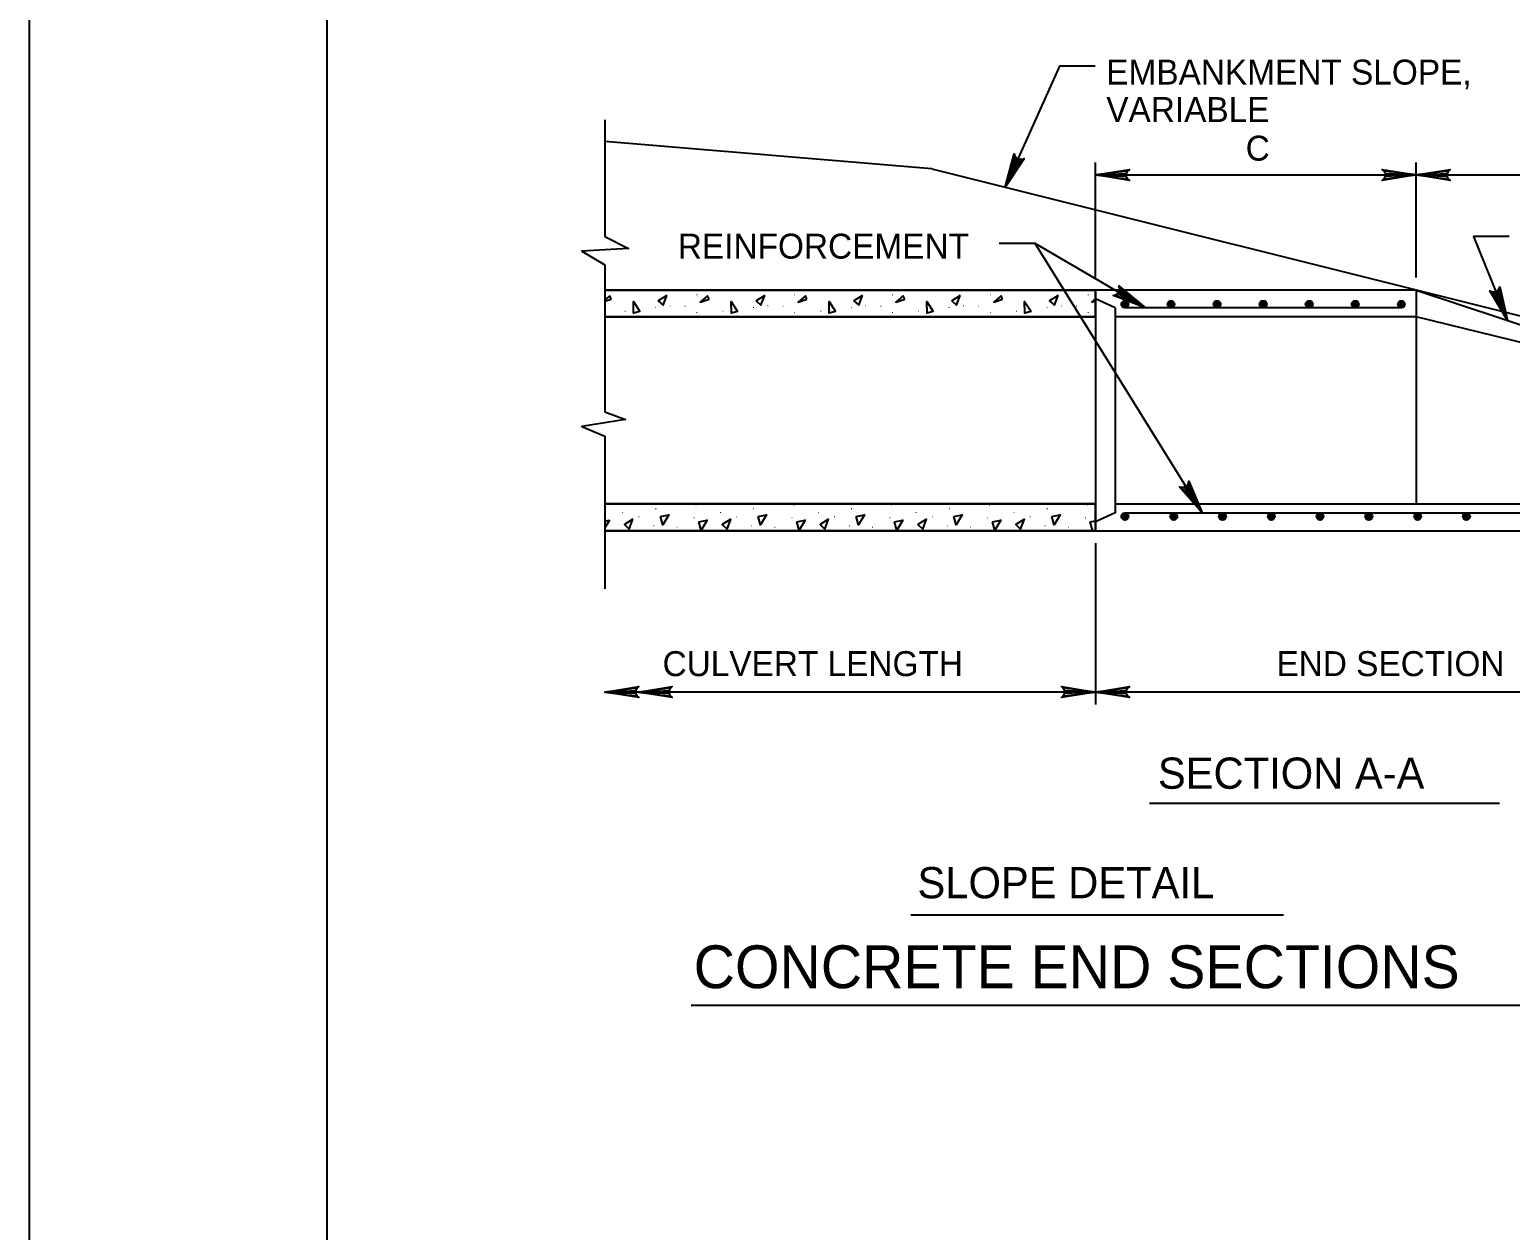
# Model space of a CAD drawing. Extents: x -17 to 888, y -473 to 715.
# Drawn here: x -17.2 to 182.2, y 391.7 to 553.3 of the extents above; entities that cross this region are included whole.
import ezdxf

# ---------------------------------------------------------------- set-up
doc = ezdxf.new("R2010")
doc.units = 0
for name, color, linetype in [('1', 7, 'Continuous'), ('2', 7, 'Continuous'), ('3', 7, 'Continuous'), ('PLT-BNDY', 7, 'Continuous')]:
    doc.layers.add(name, color=color, linetype=linetype)

msp = doc.modelspace()

# ---------------------------------------------------------------- linework, layer by layer
at = {"layer": '1'}
msp.add_lwpolyline([(808.79, 135.89), (808.79, 699.89), (22.79, 699.89), (22.79, 135.89), (808.79, 135.89), (808.79, 162.25), (608.79, 162.25), (608.79, 226.93), (808.79, 226.93), (808.79, 255.89), (608.79, 255.89), (608.79, 135.89), (687.6, 135.89), (687.6, 162.25), (687.6, 135.89), (764.6, 135.89), (764.6, 162.25), (764.6, 149.93), (808.79, 149.93)], dxfattribs=at)
at = {"layer": '2'}
for p, q in [((60.24, 541.13), (60.24, 525.42)), ((104.28, 534.53), (60.24, 538.2)), ((104.28, 534.53), (225.39, 504.25)), ((126.28, 519.91), (126.28, 535.4)), ((169.48, 519.91), (169.48, 535.4)), ((126.28, 533.72), (157.32, 533.72)), ((157.32, 533.72), (169.48, 533.72)), ((169.48, 533.72), (200.52, 533.72)), ((60.24, 521.63), (60.24, 501.82)), ((128.96, 515.83), (126.28, 517.02)), ((129.86, 516.23), (130.38, 516.71)), ((130.65, 516.5), (129.86, 516.23)), ((130.38, 516.71), (129.91, 516.57)), ((129.96, 516.04), (129.96, 516.5)), ((129.96, 516.5), (130.15, 515.94)), ((130.15, 515.94), (130.19, 516.62)), ((130.19, 516.62), (130.32, 515.91)), ((130.21, 515.91), (130.65, 516.5)), ((130.32, 515.91), (130.3, 516.7)), ((130.3, 516.7), (130.51, 516)), ((130.51, 516), (130.5, 516.65)), ((130.5, 516.65), (130.65, 516.25)), ((136.07, 516.23), (136.58, 516.71)), ((136.85, 516.5), (136.07, 516.23)), ((136.58, 516.71), (136.11, 516.57)), ((136.17, 516.04), (136.17, 516.5)), ((136.17, 516.5), (136.35, 515.94)), ((136.35, 515.94), (136.39, 516.62)), ((136.39, 516.62), (136.53, 515.91)), ((136.42, 515.91), (136.85, 516.5)), ((136.53, 515.91), (136.5, 516.7)), ((136.5, 516.7), (136.71, 516)), ((136.71, 516), (136.7, 516.65)), ((136.7, 516.65), (136.85, 516.25)), ((142.27, 516.23), (142.78, 516.71)), ((143.06, 516.5), (142.27, 516.23)), ((142.78, 516.71), (142.32, 516.57)), ((142.37, 516.04), (142.37, 516.5)), ((142.37, 516.5), (142.56, 515.94)), ((142.56, 515.94), (142.59, 516.62)), ((142.59, 516.62), (142.73, 515.91)), ((142.62, 515.91), (143.06, 516.5)), ((142.73, 515.91), (142.7, 516.7)), ((142.7, 516.7), (142.92, 516)), ((142.92, 516), (142.9, 516.65)), ((142.9, 516.65), (143.06, 516.25)), ((148.47, 516.23), (148.98, 516.71)), ((149.26, 516.5), (148.47, 516.23)), ((148.98, 516.71), (148.52, 516.57)), ((148.57, 516.04), (148.57, 516.5)), ((148.57, 516.5), (148.76, 515.94)), ((148.76, 515.94), (148.8, 516.62)), ((148.8, 516.62), (148.93, 515.91)), ((148.82, 515.91), (149.26, 516.5)), ((148.93, 515.91), (148.9, 516.7)), ((148.9, 516.7), (149.12, 516)), ((149.12, 516), (149.1, 516.65)), ((149.1, 516.65), (149.26, 516.25)), ((154.67, 516.23), (155.19, 516.71)), ((155.46, 516.5), (154.67, 516.23)), ((155.19, 516.71), (154.72, 516.57)), ((154.77, 516.04), (154.77, 516.5)), ((154.77, 516.5), (154.96, 515.94)), ((154.96, 515.94), (155, 516.62)), ((155, 516.62), (155.13, 515.91)), ((155.02, 515.91), (155.46, 516.5)), ((155.13, 515.91), (155.1, 516.7)), ((155.1, 516.7), (155.32, 516)), ((155.32, 516), (155.31, 516.65)), ((155.31, 516.65), (155.46, 516.25)), ((160.87, 516.23), (161.39, 516.71)), ((161.66, 516.5), (160.87, 516.23)), ((161.39, 516.71), (160.92, 516.57)), ((160.98, 516.04), (160.98, 516.5)), ((160.98, 516.5), (161.16, 515.94)), ((161.16, 515.94), (161.2, 516.62)), ((161.2, 516.62), (161.34, 515.91)), ((161.23, 515.91), (161.66, 516.5)), ((161.34, 515.91), (161.31, 516.7)), ((161.31, 516.7), (161.52, 516)), ((161.52, 516), (161.51, 516.65)), ((161.51, 516.65), (161.66, 516.25)), ((167.08, 516.23), (167.59, 516.71)), ((167.86, 516.5), (167.08, 516.23)), ((167.59, 516.71), (167.12, 516.57)), ((167.18, 516.04), (167.18, 516.5)), ((167.18, 516.5), (167.36, 515.94)), ((167.36, 515.94), (167.4, 516.62)), ((167.4, 516.62), (167.54, 515.91)), ((167.43, 515.91), (167.86, 516.5)), ((167.54, 515.91), (167.51, 516.7)), ((167.51, 516.7), (167.72, 516)), ((167.72, 516), (167.71, 516.65)), ((167.71, 516.65), (167.86, 516.25)), ((169.48, 518.23), (210.22, 504.65)), ((130.65, 516.25), (130.21, 515.91)), ((130.26, 516.31), (130.26, 516.31)), ((130.26, 515.83), (130.26, 515.83)), ((136.85, 516.25), (136.42, 515.91)), ((136.46, 516.31), (136.46, 516.31)), ((136.46, 515.83), (136.46, 515.83)), ((143.06, 516.25), (142.62, 515.91)), ((142.67, 516.31), (142.67, 516.31)), ((142.67, 515.83), (142.67, 515.83)), ((149.26, 516.25), (148.82, 515.91)), ((148.87, 516.31), (148.87, 516.31)), ((148.87, 515.83), (148.87, 515.83)), ((155.46, 516.25), (155.02, 515.91)), ((155.07, 516.31), (155.07, 516.31)), ((155.07, 515.83), (155.07, 515.83)), ((161.66, 516.25), (161.23, 515.91)), ((161.27, 516.31), (161.27, 516.31)), ((161.27, 515.83), (161.27, 515.83)), ((167.86, 516.25), (167.43, 515.91)), ((167.48, 516.31), (167.48, 516.31)), ((167.48, 515.83), (167.48, 515.83)), ((210.22, 504.65), (169.48, 514.63)), ((169.48, 502.03), (169.48, 502.03)), ((60.24, 498.57), (60.24, 478)), ((128.96, 488.23), (126.28, 487.03)), ((129.86, 487.67), (130.38, 488.15)), ((130.65, 487.94), (129.86, 487.67)), ((130.38, 488.15), (129.91, 488.01)), ((129.96, 487.48), (129.96, 487.94)), ((129.96, 487.94), (130.15, 487.38)), ((130.15, 487.38), (130.19, 488.06)), ((130.19, 488.06), (130.32, 487.35)), ((130.21, 487.35), (130.65, 487.94)), ((130.65, 487.69), (130.21, 487.35)), ((130.26, 488.23), (130.26, 488.23)), ((130.26, 487.75), (130.26, 487.75)), ((130.32, 487.35), (130.3, 488.14)), ((130.3, 488.14), (130.51, 487.44)), ((130.51, 487.44), (130.5, 488.09)), ((130.5, 488.09), (130.65, 487.69)), ((136.43, 487.67), (136.95, 488.15)), ((137.22, 487.94), (136.43, 487.67)), ((136.95, 488.15), (136.48, 488.01)), ((136.53, 487.48), (136.53, 487.94)), ((136.53, 487.94), (136.72, 487.38)), ((136.72, 487.38), (136.76, 488.06)), ((136.76, 488.06), (136.89, 487.35)), ((136.78, 487.35), (137.22, 487.94)), ((137.22, 487.69), (136.78, 487.35)), ((136.83, 488.23), (136.83, 488.23)), ((136.83, 487.75), (136.83, 487.75)), ((136.89, 487.35), (136.86, 488.14)), ((136.86, 488.14), (137.08, 487.44)), ((137.08, 487.44), (137.07, 488.09)), ((137.07, 488.09), (137.22, 487.69)), ((143, 487.67), (143.51, 488.15)), ((143.79, 487.94), (143, 487.67)), ((143.51, 488.15), (143.05, 488.01)), ((143.1, 487.48), (143.1, 487.94)), ((143.1, 487.94), (143.29, 487.38)), ((143.29, 487.38), (143.33, 488.06)), ((143.33, 488.06), (143.46, 487.35)), ((143.35, 487.35), (143.79, 487.94)), ((143.79, 487.69), (143.35, 487.35)), ((143.4, 488.23), (143.4, 488.23)), ((143.4, 487.75), (143.4, 487.75)), ((143.46, 487.35), (143.43, 488.14)), ((143.43, 488.14), (143.65, 487.44)), ((143.65, 487.44), (143.63, 488.09)), ((143.63, 488.09), (143.79, 487.69)), ((149.57, 487.67), (150.08, 488.15)), ((150.35, 487.94), (149.57, 487.67)), ((150.08, 488.15), (149.62, 488.01)), ((149.67, 487.48), (149.67, 487.94)), ((149.67, 487.94), (149.86, 487.38)), ((149.86, 487.38), (149.89, 488.06)), ((149.89, 488.06), (150.03, 487.35)), ((149.92, 487.35), (150.35, 487.94)), ((150.35, 487.69), (149.92, 487.35)), ((149.97, 488.23), (149.97, 488.23)), ((149.97, 487.75), (149.97, 487.75)), ((150.03, 487.35), (150, 488.14)), ((150, 488.14), (150.22, 487.44)), ((150.22, 487.44), (150.2, 488.09)), ((150.2, 488.09), (150.35, 487.69)), ((156.14, 487.67), (156.65, 488.15)), ((156.92, 487.94), (156.14, 487.67)), ((156.65, 488.15), (156.18, 488.01)), ((156.24, 487.48), (156.24, 487.94)), ((156.24, 487.94), (156.42, 487.38)), ((156.42, 487.38), (156.46, 488.06)), ((156.46, 488.06), (156.6, 487.35)), ((156.49, 487.35), (156.92, 487.94)), ((156.92, 487.69), (156.49, 487.35)), ((156.53, 488.23), (156.53, 488.23)), ((156.53, 487.75), (156.53, 487.75)), ((156.6, 487.35), (156.57, 488.14)), ((156.57, 488.14), (156.78, 487.44)), ((156.78, 487.44), (156.77, 488.09)), ((156.77, 488.09), (156.92, 487.69)), ((162.7, 487.67), (163.22, 488.15)), ((163.49, 487.94), (162.7, 487.67)), ((163.22, 488.15), (162.75, 488.01)), ((162.8, 487.48), (162.8, 487.94)), ((162.8, 487.94), (162.99, 487.38)), ((162.99, 487.38), (163.03, 488.06)), ((163.03, 488.06), (163.16, 487.35)), ((163.05, 487.35), (163.49, 487.94)), ((163.49, 487.69), (163.05, 487.35)), ((163.1, 488.23), (163.1, 488.23)), ((163.1, 487.75), (163.1, 487.75)), ((163.16, 487.35), (163.14, 488.14)), ((163.14, 488.14), (163.35, 487.44)), ((163.35, 487.44), (163.34, 488.09)), ((163.34, 488.09), (163.49, 487.69)), ((169.27, 487.67), (169.79, 488.15)), ((170.06, 487.94), (169.27, 487.67)), ((169.79, 488.15), (169.32, 488.01)), ((169.37, 487.48), (169.37, 487.94)), ((169.37, 487.94), (169.56, 487.38)), ((169.56, 487.38), (169.6, 488.06)), ((169.6, 488.06), (169.73, 487.35)), ((169.62, 487.35), (170.06, 487.94)), ((170.06, 487.69), (169.62, 487.35)), ((169.67, 488.23), (169.67, 488.23)), ((169.67, 487.75), (169.67, 487.75)), ((169.73, 487.35), (169.7, 488.14)), ((169.7, 488.14), (169.92, 487.44)), ((169.92, 487.44), (169.91, 488.09)), ((169.91, 488.09), (170.06, 487.69)), ((175.84, 487.67), (176.35, 488.15)), ((176.63, 487.94), (175.84, 487.67)), ((176.35, 488.15), (175.89, 488.01)), ((175.94, 487.48), (175.94, 487.94)), ((175.94, 487.94), (176.13, 487.38)), ((176.13, 487.38), (176.17, 488.06)), ((176.17, 488.06), (176.3, 487.35)), ((176.19, 487.35), (176.63, 487.94)), ((176.63, 487.69), (176.19, 487.35)), ((176.24, 488.23), (176.24, 488.23)), ((176.24, 487.75), (176.24, 487.75)), ((176.3, 487.35), (176.27, 488.14)), ((176.27, 488.14), (176.49, 487.44)), ((176.49, 487.44), (176.47, 488.09)), ((176.47, 488.09), (176.63, 487.69)), ((61.92, 485.83), (214.36, 485.83)), ((126.28, 484.15), (126.28, 462.44)), ((102.56, 464.12), (60.24, 464.12)), ((126.28, 464.12), (102.56, 464.12)), ((178.92, 464.12), (126.28, 464.12)), ((212.68, 464.12), (178.92, 464.12))]:
    msp.add_line(p, q, dxfattribs=at)
for points in [[(126.26, 548.34), (121.46, 548.34), (114.13, 532.07)], [(116.42, 535.81), (116.06, 535.8), (114.13, 532.07), (116.42, 535.81), (116.68, 535.94), (114.13, 532.07), (115.66, 535.97), (115.44, 536.24), (114.13, 532.07), (115.35, 536.54), (115.44, 536.24)], [(130.64, 533.17), (130.47, 533.48), (126.28, 533.72), (130.64, 533.17), (130.86, 532.98), (126.28, 533.72), (130.47, 533.92), (130.62, 534.24), (126.28, 533.72), (130.86, 534.44), (130.62, 534.24)], [(165.12, 534.26), (165.28, 533.95), (169.48, 533.72), (165.12, 534.26), (164.9, 534.45), (169.48, 533.72), (165.28, 533.51), (165.13, 533.2), (169.48, 533.72), (164.9, 532.99), (165.13, 533.2)], [(173.84, 533.17), (173.67, 533.48), (169.48, 533.72), (173.84, 533.17), (174.06, 532.98), (169.48, 533.72), (173.67, 533.92), (173.82, 534.24), (169.48, 533.72), (174.06, 534.44), (173.82, 534.24)], [(60.24, 525.42), (63.42, 523.83), (57.15, 523.45), (60.24, 521.63)], [(113.31, 524.54), (118.11, 524.54), (133.01, 515.83)], [(118.11, 524.54), (140.64, 488.23)], [(181.99, 525.43), (177.19, 525.43), (181.77, 514.13)], [(129.52, 518.5), (129.5, 518.15), (133.01, 515.83), (129.52, 518.5), (129.42, 518.78), (133.01, 515.83), (129.28, 517.77), (128.99, 517.57), (133.01, 515.83), (128.68, 517.51), (128.99, 517.57)], [(180.64, 518.38), (180.41, 518.11), (181.77, 514.13), (180.64, 518.38), (180.73, 518.65), (181.77, 514.13), (180, 517.94), (179.66, 517.96), (181.77, 514.13), (179.37, 518.1), (179.66, 517.96)], [(60.24, 518.23), (126.28, 518.23), (126.28, 514.63), (60.24, 514.63)], [(60.9, 517.45), (60.24, 516.89)], [(60.24, 516.71), (61.1, 516.99)], [(61.1, 516.99), (60.9, 517.45)], [(126.28, 517.04), (125.77, 516.6)], [(125.77, 516.6), (126.28, 516.77)], [(169.48, 518.23), (126.28, 518.23), (126.28, 485.83), (212.68, 485.83)], [(169.48, 518.23), (169.48, 501.22)], [(128.96, 515.83), (128.96, 488.23)], [(169.48, 514.63), (128.96, 514.63)], [(167.48, 515.83), (130.26, 515.83)], [(60.24, 501.82), (63.04, 500.82), (57.15, 499.87), (60.24, 498.57)], [(169.48, 501.22), (169.48, 489.43)], [(138.8, 492.22), (138.62, 491.92), (140.64, 488.23), (138.8, 492.22), (138.85, 492.51), (140.64, 488.23), (138.25, 491.68), (137.9, 491.65), (140.64, 488.23), (137.6, 491.74), (137.9, 491.65)], [(60.24, 489.43), (126.28, 489.43), (126.28, 485.83), (60.24, 485.83)], [(128.96, 489.43), (212.68, 489.43)], [(60.24, 487.13), (60.86, 487.25)], [(60.86, 487.25), (60.24, 486.22)], [(125.6, 487.03), (126.28, 487.17)], [(125.91, 485.92), (125.6, 487.03)], [(130.26, 488.23), (209.08, 488.23)], [(64.6, 463.57), (64.44, 463.89), (60.24, 464.12), (64.6, 463.57), (64.82, 463.38), (60.24, 464.12), (64.44, 464.33), (64.59, 464.64), (60.24, 464.12), (64.82, 464.85), (64.59, 464.64)], [(69.1, 463.57), (68.94, 463.89), (64.74, 464.12), (69.1, 463.57), (69.32, 463.38), (64.74, 464.12), (68.94, 464.33), (69.09, 464.64), (64.74, 464.12), (69.32, 464.85), (69.09, 464.64)], [(121.92, 464.67), (122.08, 464.35), (126.28, 464.12), (121.92, 464.67), (121.7, 464.86), (126.28, 464.12), (122.08, 463.91), (121.93, 463.6), (126.28, 464.12), (121.7, 463.39), (121.93, 463.6)], [(130.64, 463.57), (130.47, 463.89), (126.28, 464.12), (130.64, 463.57), (130.86, 463.38), (126.28, 464.12), (130.47, 464.33), (130.62, 464.64), (126.28, 464.12), (130.86, 464.85), (130.62, 464.64)]]:
    msp.add_lwpolyline(points, dxfattribs=at)
for points in [[(60.24, 518.23), (60.24, 514.63), (126.28, 514.63), (126.28, 518.23)], [(64.94, 515.32), (64.11, 515.13), (64.08, 516.66)], [(68.59, 517.48), (67.44, 516.76), (68.09, 516.18)], [(74.27, 516.99), (74.07, 517.45), (73.08, 516.6)], [(78.11, 515.32), (77.28, 515.13), (77.25, 516.66)], [(81.76, 517.48), (80.61, 516.76), (81.26, 516.18)], [(87.44, 516.99), (87.24, 517.45), (86.25, 516.6)], [(91.28, 515.32), (90.45, 515.13), (90.42, 516.66)], [(94.93, 517.48), (93.78, 516.76), (94.43, 516.18)], [(100.61, 516.99), (100.41, 517.45), (99.42, 516.6)], [(104.45, 515.32), (103.62, 515.13), (103.59, 516.66)], [(108.1, 517.48), (106.95, 516.76), (107.6, 516.18)], [(113.79, 516.99), (113.58, 517.45), (112.6, 516.6)], [(117.63, 515.32), (116.79, 515.13), (116.76, 516.66)], [(121.27, 517.48), (120.12, 516.76), (120.77, 516.18)], [(60.24, 489.43), (60.24, 485.83), (126.28, 485.83), (126.28, 489.43)], [(64.03, 487.37), (62.88, 486.65), (63.53, 486.06)], [(67.73, 487.74), (68.85, 487.96), (68.04, 486.63)], [(72.91, 487.03), (74.03, 487.25), (73.23, 485.92)], [(77.2, 487.37), (76.05, 486.65), (76.7, 486.06)], [(80.9, 487.74), (82.02, 487.96), (81.21, 486.63)], [(86.08, 487.03), (87.2, 487.25), (86.4, 485.92)], [(90.37, 487.37), (89.22, 486.65), (89.87, 486.06)], [(94.07, 487.74), (95.19, 487.96), (94.39, 486.63)], [(99.25, 487.03), (100.38, 487.25), (99.57, 485.92)], [(103.54, 487.37), (102.39, 486.65), (103.04, 486.06)], [(107.24, 487.74), (108.36, 487.96), (107.56, 486.63)], [(112.42, 487.03), (113.55, 487.25), (112.74, 485.92)], [(116.72, 487.37), (115.56, 486.65), (116.22, 486.06)], [(120.41, 487.74), (121.53, 487.96), (120.73, 486.63)]]:
    msp.add_lwpolyline(points, close=True, dxfattribs=at)
for centre in [(130.26, 516.31), (136.46, 516.31), (142.67, 516.31), (148.87, 516.31), (155.07, 516.31), (161.27, 516.31), (167.48, 516.31), (130.26, 487.75), (136.83, 487.75), (143.4, 487.75), (149.97, 487.75), (156.53, 487.75), (163.1, 487.75), (169.67, 487.75), (176.24, 487.75)]:
    msp.add_circle(centre, 0.48, dxfattribs=at)
at = {"layer": '3'}
for p, q in [((133.55, 449.15), (180.67, 449.15)), ((101.45, 434.14), (151.59, 434.14)), ((71.88, 421.95), (190.27, 421.95))]:
    msp.add_line(p, q, dxfattribs=at)
at = {"layer": 'PLT-BNDY'}
msp.add_lwpolyline([(-17.21, 714.89), (823.79, 714.89), (823.79, 120.89), (-17.21, 120.89)], close=True, dxfattribs=at)

# ---------------------------------------------------------------- texts
at = {"layer": '2'}
for p in [(72.46, 517.52), (85.63, 517.52), (98.8, 517.52), (111.97, 517.52), (125.14, 517.52), (62.81, 515.3), (66.92, 515.8), (68.85, 516.02), (70.88, 515.97), (72.46, 515.14), (75.98, 515.3), (80.09, 515.8), (82.02, 516.02), (84.05, 515.97), (85.63, 515.14), (89.15, 515.3), (93.26, 515.8), (95.19, 516.02), (97.23, 515.97), (98.8, 515.14), (102.32, 515.3), (106.43, 515.8), (108.36, 516.02), (110.4, 515.97), (111.97, 515.14), (115.49, 515.3), (119.6, 515.8), (121.53, 516.02), (123.57, 515.97), (125.14, 515.14), (66.95, 488.73), (72.35, 489.2), (80.12, 488.73), (85.52, 489.2), (93.29, 488.73), (98.7, 489.2), (106.46, 488.73), (111.87, 489.2), (119.63, 488.73), (125.04, 489.2), (62.48, 488.23), (64.64, 487.65), (66.68, 486.4), (72.1, 487.49), (72.1, 487.49), (75.65, 488.23), (77.82, 487.65), (79.85, 486.4), (85.28, 487.49), (85.28, 487.49), (88.82, 488.23), (90.99, 487.65), (93.02, 486.4), (98.45, 487.49), (98.45, 487.49), (101.99, 488.23), (104.16, 487.65), (106.19, 486.4), (111.62, 487.49), (111.62, 487.49), (115.16, 488.23), (117.33, 487.65), (119.36, 486.4), (124.79, 487.49), (124.79, 487.49), (69.78, 486.22), (82.95, 486.22), (96.12, 486.22), (109.29, 486.22), (122.47, 486.22)]:
    msp.add_text('.', height=0.893, dxfattribs=at).set_placement(p)
at = {"layer": '3'}
for s, height, p in [('EMBANKMENT SLOPE,', 3.36, (127.75, 545.88)), ('VARIABLE', 3.36, (127.75, 540.84)), ('C', 3.36, (146.52, 535.64)), ('REINFORCEMENT', 3.36, (70.07, 522.45)), ('CULVERT LENGTH', 3.36, (68.01, 466.26)), ('END SECTION', 3.36, (150.66, 466.26)), ('SECTION A-A', 4.2, (134.7, 451.1)), ('SLOPE DETAIL', 4.2, (102.33, 436.36)), ('CONCRETE END SECTIONS', 5.76, (72.2, 424.26))]:
    msp.add_text(s, height=height, dxfattribs=at).set_placement(p)

doc.saveas('drawing.dxf')
